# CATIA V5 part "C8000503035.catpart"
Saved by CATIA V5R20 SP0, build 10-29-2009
Part number: C8000503035
Source: Unknown
Property "A": "45"
Property "ARTICLENO": "C8000503035"
Property "B": "22"
Property "BOMINFO": "C8000503035"
Property "C": "65"
Property "CA": "C8000503035"
Property "D1": "75"
Property "DES": "ROTATING EYEBOLT WITH RING Ton 5,3 M30x35"
Property "E": "80"
Property "H": "165"
Property "L": "35"
Property "LINA": "C8000503035"
Property "NB": "C8000503035"
Property "NBSYN": "$CODE."
Property "NN": "C800"
Property "NT": "Rotating eyebolt with ring"
Property "SIZE": "M30"
Property "SUPPLIER": "CF"
Property "SW": "65"
Property "WEIGHT": "2230"
Property "WLL": "5.30"
Bounding box of the stored display mesh (mm): x -44.333 to 44.5, y -35 to 186.644, z -37.5 to 37.5
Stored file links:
  C:\Users\Utente\Desktop\3D files 800\C8000503035.catpart
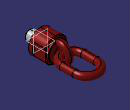
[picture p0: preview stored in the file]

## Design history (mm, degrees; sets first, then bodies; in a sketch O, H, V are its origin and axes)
Body1 "Geometry.1" (main body)
  Solid1 "C8000503035.catpart": solid without history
